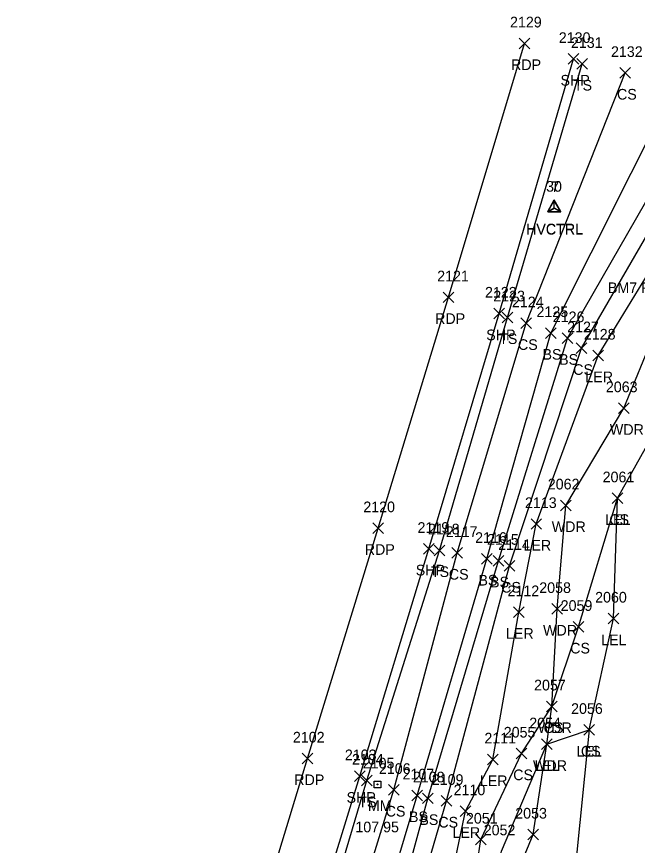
# Model space of a CAD drawing. Extents: x 1483143 to 1488182, y 802902 to 807581.
# Drawn here: x 1487999.7 to 1488116.3, y 807041.9 to 807197.5 of the extents above; entities that cross this region are included whole.
import ezdxf

# ---------------------------------------------------------------- set-up
doc = ezdxf.new("R2010")
doc.units = 0
for name, color, linetype in [('C_A', 7, 'Continuous'), ('C_C', 7, 'Continuous'), ('C_I', 7, 'Continuous'), ('CPSM', 7, 'Continuous'), ('L_A', 7, 'Continuous'), ('L_I', 7, 'Continuous'), ('L_TIC', 7, 'Continuous'), ('LARO', 7, 'Continuous'), ('LAWA', 7, 'Continuous'), ('LELB', 7, 'Continuous'), ('P_A', 7, 'Continuous'), ('P_I', 7, 'Continuous'), ('P_TIC', 7, 'Continuous'), ('PET', 7, 'Continuous'), ('PSP', 7, 'Continuous'), ('S_A', 7, 'Continuous'), ('S_C', 7, 'Continuous'), ('S_I', 7, 'Continuous'), ('SRM', 7, 'Continuous')]:
    doc.layers.add(name, color=color, linetype=linetype)

msp = doc.modelspace()

# ---------------------------------------------------------------- linework, layer by layer
at = {"layer": 'CPSM'}
for p, q in [((1488099.44, 807160.93), (1488100.69, 807163.1)), ((1488099.44, 807160.86), (1488100.69, 807163.02)), ((1488101.94, 807160.93), (1488100.69, 807163.1)), ((1488100.69, 807161.65), (1488100.69, 807163.1)), ((1488101.94, 807160.86), (1488100.69, 807163.02)), ((1488100.69, 807161.58), (1488100.69, 807163.02)), ((1488099.44, 807160.93), (1488100.69, 807161.65)), ((1488099.44, 807160.86), (1488100.69, 807161.58)), ((1488099.44, 807160.93), (1488101.94, 807160.93)), ((1488099.44, 807160.86), (1488101.94, 807160.86)), ((1488100.69, 807161.65), (1488100.69, 807161.65)), ((1488100.69, 807161.65), (1488101.94, 807160.93)), ((1488100.69, 807161.58), (1488100.69, 807161.58)), ((1488100.69, 807161.58), (1488101.94, 807160.86))]:
    msp.add_line(p, q, dxfattribs=at)
at = {"layer": 'L_TIC'}
for points in [[(1488104.94, 807187.64), (1488106.94, 807189.64)], [(1488106.94, 807187.64), (1488104.94, 807189.64)], [(1488113.02, 807185.94), (1488115.02, 807187.94)], [(1488115.02, 807185.94), (1488113.02, 807187.94)], [(1488090.92, 807140.06), (1488092.92, 807142.06)], [(1488092.92, 807140.06), (1488090.92, 807142.06)], [(1488094.42, 807138.95), (1488096.42, 807140.95)], [(1488096.42, 807138.95), (1488094.42, 807140.95)], [(1488099.03, 807137.12), (1488101.03, 807139.12)], [(1488101.03, 807137.12), (1488099.03, 807139.12)], [(1488102.15, 807136.16), (1488104.15, 807138.16)], [(1488104.15, 807136.16), (1488102.15, 807138.16)], [(1488104.79, 807134.26), (1488106.79, 807136.26)], [(1488106.79, 807134.26), (1488104.79, 807136.26)], [(1488107.93, 807132.89), (1488109.93, 807134.89)], [(1488109.93, 807132.89), (1488107.93, 807134.89)], [(1488112.75, 807123.01), (1488114.75, 807125.01)], [(1488114.75, 807123.01), (1488112.75, 807125.01)], [(1488111.58, 807106.1), (1488113.58, 807108.1)], [(1488113.58, 807106.1), (1488111.58, 807108.1)], [(1488111.58, 807106.1), (1488113.58, 807108.1)], [(1488113.58, 807106.1), (1488111.58, 807108.1)], [(1488101.84, 807104.76), (1488103.84, 807106.76)], [(1488103.84, 807104.76), (1488101.84, 807106.76)], [(1488096.31, 807101.27), (1488098.31, 807103.27)], [(1488098.31, 807101.27), (1488096.31, 807103.27)], [(1488078.1, 807096.32), (1488080.1, 807098.32)], [(1488080.1, 807096.32), (1488078.1, 807098.32)], [(1488081.44, 807095.83), (1488083.44, 807097.83)], [(1488083.44, 807095.83), (1488081.44, 807097.83)], [(1488087, 807094.72), (1488089, 807096.72)], [(1488089, 807094.72), (1488087, 807096.72)], [(1488089.18, 807094.37), (1488091.18, 807096.37)], [(1488091.18, 807094.37), (1488089.18, 807096.37)], [(1488091.26, 807093.39), (1488093.26, 807095.39)], [(1488093.26, 807093.39), (1488091.26, 807095.39)], [(1488093.03, 807084.72), (1488095.03, 807086.72)], [(1488095.03, 807084.72), (1488093.03, 807086.72)], [(1488100.2, 807085.32), (1488102.2, 807087.32)], [(1488102.2, 807085.32), (1488100.2, 807087.32)], [(1488110.83, 807083.52), (1488112.83, 807085.52)], [(1488112.83, 807083.52), (1488110.83, 807085.52)], [(1488104.23, 807081.96), (1488106.23, 807083.96)], [(1488106.23, 807081.96), (1488104.23, 807083.96)], [(1488099.23, 807067.03), (1488101.23, 807069.03)], [(1488101.23, 807067.03), (1488099.23, 807069.03)], [(1488099.23, 807067.03), (1488101.23, 807069.03)], [(1488101.23, 807067.03), (1488099.23, 807069.03)], [(1488106.24, 807062.62), (1488108.24, 807064.62)], [(1488108.24, 807062.62), (1488106.24, 807064.62)], [(1488106.24, 807062.62), (1488108.24, 807064.62)], [(1488108.24, 807062.62), (1488106.24, 807064.62)], [(1488098.31, 807059.91), (1488100.31, 807061.91)], [(1488100.31, 807059.91), (1488098.31, 807061.91)], [(1488098.31, 807059.91), (1488100.31, 807061.91)], [(1488100.31, 807059.91), (1488098.31, 807061.91)], [(1488093.53, 807058.18), (1488095.53, 807060.18)], [(1488095.53, 807058.18), (1488093.53, 807060.18)], [(1488088.12, 807057.07), (1488090.12, 807059.07)], [(1488090.12, 807057.07), (1488088.12, 807059.07)], [(1488064.46, 807053.1), (1488066.46, 807055.1)], [(1488066.46, 807053.1), (1488064.46, 807055.1)], [(1488069.58, 807051.35), (1488071.58, 807053.35)], [(1488071.58, 807051.35), (1488069.58, 807053.35)], [(1488073.95, 807050.31), (1488075.95, 807052.31)], [(1488075.95, 807050.31), (1488073.95, 807052.31)], [(1488075.91, 807049.77), (1488077.91, 807051.77)], [(1488077.91, 807049.77), (1488075.91, 807051.77)], [(1488079.46, 807049.29), (1488081.46, 807051.29)], [(1488081.46, 807049.29), (1488079.46, 807051.29)], [(1488082.99, 807047.35), (1488084.99, 807049.35)], [(1488084.99, 807047.35), (1488082.99, 807049.35)], [(1488095.69, 807042.97), (1488097.69, 807044.97)], [(1488097.69, 807042.97), (1488095.69, 807044.97)], [(1488085.86, 807042.03), (1488087.86, 807044.03)], [(1488087.86, 807042.03), (1488085.86, 807044.03)]]:
    msp.add_lwpolyline(points, dxfattribs=at)
at = {"layer": 'LARO'}
for points in [[(1488037.4, 806905.47), (1488041.65, 806915.63), (1488047.6, 806920.57), (1488046.62, 806934.71), (1488052.04, 806951.56), (1488058.64, 806974.33), (1488067.63, 806991.16), (1488072.23, 806999.37), (1488073.8, 807008.16), (1488079.91, 807014.12), (1488080.77, 807032.91), (1488083.99, 807048.35), (1488089.12, 807058.07), (1488094.03, 807085.72), (1488097.31, 807102.27), (1488108.93, 807133.89), (1488121.99, 807155.3), (1488125.4, 807152.3), (1488130.41, 807144.38)], [(1488050.72, 806901.7), (1488054.57, 806915.09), (1488058.39, 806925.38), (1488058.38, 806932.99), (1488064.32, 806951.27), (1488070.59, 806959.46), (1488072.37, 806972.02), (1488078.48, 806986.93), (1488088.4, 807009.21), (1488088, 807029.33), (1488090.77, 807040.83), (1488099.31, 807060.91), (1488107.24, 807063.62), (1488111.83, 807084.52), (1488112.58, 807107.1), (1488120.46, 807121.22), (1488130.41, 807144.38)]]:
    msp.add_lwpolyline(points, dxfattribs=at)
at = {"layer": 'LAWA'}
msp.add_lwpolyline([(1488060.09, 806903.93), (1488066.6, 806927.09), (1488073.94, 806954.77), (1488083.55, 806972.96), (1488088.27, 806995.8), (1488088.4, 807009.21), (1488090.5, 807029.04), (1488096.69, 807043.97), (1488099.31, 807060.91), (1488100.23, 807068.03), (1488101.2, 807086.32), (1488102.84, 807105.76), (1488113.75, 807124.01), (1488125.4, 807152.3), (1488136.51, 807165.24), (1488139.33, 807176.91)], dxfattribs=at)
at = {"layer": 'LELB'}
for points in [[(1487827.52, 806379.6), (1487850.09, 806437.73), (1487867.87, 806481.84), (1487885.56, 806528.78), (1487894.77, 806554.11), (1487911.86, 806599.05), (1487925.11, 806635.03), (1487938.6, 806672.73), (1487954.13, 806715.2), (1487966.77, 806750.86), (1487982.82, 806798.37), (1488000.33, 806849.53), (1488013.76, 806891.57), (1488028.96, 806936.12), (1488043.22, 806981), (1488053.37, 807013.21), (1488065.46, 807054.1), (1488079.1, 807097.32), (1488091.92, 807141.06), (1488105.94, 807188.64)], [(1487831.61, 806378.23), (1487855.61, 806436.65), (1487873.41, 806477.14), (1487888.61, 806527.7), (1487900.29, 806552.66), (1487915.56, 806597.3), (1487929.53, 806633.53), (1487942.79, 806670.21), (1487957.7, 806713.57), (1487969.99, 806749.64), (1487987.61, 806796.79), (1487994.35, 806813.4), (1488006.31, 806847.85), (1488017.75, 806890.1), (1488033.51, 806934.67), (1488047.05, 806979.87), (1488058.1, 807011.89), (1488070.58, 807052.35), (1488082.44, 807096.83), (1488095.42, 807139.95), (1488114.02, 807186.94)], [(1487835.19, 806376.59), (1487859.78, 806434.97), (1487877.62, 806477.28), (1487892.57, 806526.23), (1487904.08, 806551.45), (1487919.68, 806595.15), (1487934.47, 806632.17), (1487947.69, 806668.31), (1487962.32, 806711.59), (1487973.69, 806748.32), (1487991.68, 806795.65), (1487997.75, 806809.49), (1487999.54, 806813.18), (1488009.67, 806846.56), (1488021.34, 806888.06), (1488037.67, 806932.78), (1488051.91, 806977.51), (1488062.67, 807010.29), (1488074.95, 807051.31), (1488088, 807095.72), (1488100.03, 807138.12), (1488122.67, 807183.2)], [(1487837.5, 806376), (1487863.45, 806433.38), (1487880.32, 806475.86), (1487894.61, 806525.53), (1487906.02, 806551.4), (1487922.48, 806594.15), (1487937, 806631.99), (1487949.11, 806668.02), (1487964.79, 806711), (1487978.4, 806746.47), (1487994.99, 806794.38), (1488000.35, 806808.82), (1488001.34, 806812.09), (1488011.23, 806845.63), (1488024.65, 806886.78), (1488040.19, 806931.5), (1488054.27, 806976.88), (1488065.68, 807009.57), (1488076.91, 807050.77), (1488090.18, 807095.37), (1488103.15, 807137.16), (1488127.49, 807179.54)], [(1487839.66, 806374.66), (1487865.87, 806433.14), (1487881.15, 806476.22), (1487897.55, 806523.91), (1487908.57, 806550.53), (1487926.89, 806591.97), (1487940.49, 806630.59), (1487952.54, 806666.3), (1487966.7, 806710.04), (1487981.74, 806745.96), (1487997.33, 806793.52), (1488011.64, 806832), (1488027.95, 806886.11), (1488041.92, 806927.39), (1488045.38, 806935.91), (1488056.2, 806975.87), (1488068.38, 807008.79), (1488080.46, 807050.29), (1488092.26, 807094.39), (1488105.79, 807135.26), (1488129.48, 807176.06)], [(1488043.93, 806905.8), (1488054.57, 806915.09), (1488048.86, 806918.51), (1488050.26, 806926.52), (1488054.26, 806940.91), (1488057.32, 806952.68), (1488061.43, 806965.52), (1488065.26, 806978.26), (1488072.35, 806989.31), (1488077.56, 806999.25), (1488084.51, 807008.67), (1488084.83, 807029.18), (1488086.86, 807043.03), (1488094.53, 807059.18), (1488100.23, 807068.03), (1488105.23, 807082.96), (1488112.58, 807107.1)], [(1488107.24, 807063.62), (1488102.78, 807019.53), (1488102.52, 806993.48), (1488098.25, 806971.93), (1488100.18, 806941.81), (1488099.28, 806926.81), (1488086.46, 806896.83), (1488081.97, 806885.84), (1488071.39, 806887.6), (1488071.71, 806872.37), (1488064.05, 806852.05), (1488068.8, 806843.92), (1488067.03, 806830.27), (1488057.62, 806804.31), (1488039.63, 806814.37), (1488034.14, 806816.99), (1488041.4, 806825.04)]]:
    msp.add_lwpolyline(points, dxfattribs=at)
at = {"layer": 'P_TIC'}
for points in [[(1488094.07, 807191.49), (1488096.07, 807193.49)], [(1488096.07, 807191.49), (1488094.07, 807193.49)], [(1488103.31, 807188.57), (1488105.31, 807190.57)], [(1488105.31, 807188.57), (1488103.31, 807190.57)], [(1488079.81, 807143.82), (1488081.81, 807145.82)], [(1488081.81, 807143.82), (1488079.81, 807145.82)], [(1488089.36, 807140.77), (1488091.36, 807142.77)], [(1488091.36, 807140.77), (1488089.36, 807142.77)], [(1488066.6, 807100.48), (1488068.6, 807102.48)], [(1488068.6, 807100.48), (1488066.6, 807102.48)], [(1488076.14, 807096.61), (1488078.14, 807098.61)], [(1488078.14, 807096.61), (1488076.14, 807098.61)], [(1488053.37, 807057.25), (1488055.37, 807059.25)], [(1488055.37, 807057.25), (1488053.37, 807059.25)], [(1488063.14, 807053.93), (1488065.14, 807055.93)], [(1488065.14, 807053.93), (1488063.14, 807055.93)]]:
    msp.add_lwpolyline(points, dxfattribs=at)
at = {"layer": 'PET'}
msp.add_lwpolyline([(1487817.05, 806384.04), (1487839.67, 806441.4), (1487857.48, 806486.15), (1487875.5, 806533.55), (1487884.95, 806558.16), (1487901.52, 806603.65), (1487914.56, 806639.6), (1487927.99, 806676.8), (1487943.06, 806720.01), (1487955.19, 806754.64), (1487971.37, 806801.63), (1487988.85, 806854.11), (1488002.85, 806896.07), (1488017.7, 806940.87), (1488031.56, 806984.9), (1488041.8, 807017.08), (1488054.37, 807058.25), (1488067.6, 807101.48), (1488080.81, 807144.82), (1488095.07, 807192.49)], dxfattribs=at)
at = {"layer": 'PSP'}
msp.add_lwpolyline([(1487825.55, 806380.21), (1487847.81, 806437.56), (1487866.19, 806483.39), (1487884.04, 806529.78), (1487893.44, 806554.46), (1487910.05, 806599.89), (1487923.16, 806635.65), (1487936.98, 806673.57), (1487951.99, 806715.79), (1487964.7, 806751.7), (1487980.81, 806798.97), (1487998.23, 806850.18), (1488012.19, 806892.24), (1488027.11, 806936.91), (1488041.21, 806981.53), (1488051.31, 807013.35), (1488064.14, 807054.93), (1488077.14, 807097.61), (1488090.36, 807141.77), (1488104.31, 807189.57)], dxfattribs=at)
at = {"layer": 'SRM'}
msp.add_lwpolyline([(1488066.86, 807054.02), (1488068.11, 807054.02), (1488068.11, 807052.77), (1488066.86, 807052.77)], close=True, dxfattribs=at)
msp.add_circle((1488067.48, 807053.39), 0.0833, dxfattribs=at)

# ---------------------------------------------------------------- texts
at = {"layer": 'C_A'}
for p in [(1488095.38, 807156.65), (1488095.38, 807156.58)]:
    msp.add_text('HVCTRL', height=2, dxfattribs=at).set_placement(p)
at = {"layer": 'C_C'}
msp.add_text('BM7 RRSIR M.ASH ELV', height=2, dxfattribs=at).set_placement((1488110.75, 807145.62))
at = {"layer": 'C_I'}
for s, p in [('30', (1488099.14, 807164.65)), ('7', (1488100.12, 807164.58))]:
    msp.add_text(s, height=2, dxfattribs=at).set_placement(p)
at = {"layer": 'L_A'}
for s, p in [('TS', (1488104.35, 807183.64)), ('CS', (1488112.46, 807181.94)), ('TS', (1488090.33, 807136.06)), ('CS', (1488093.86, 807134.95)), ('BS', (1488098.47, 807133.12)), ('BS', (1488101.59, 807132.16)), ('CS', (1488104.23, 807130.26)), ('LER', (1488106.51, 807128.89)), ('WDR', (1488111.12, 807119.01)), ('LEL', (1488110.22, 807102.1)), ('CS', (1488111.02, 807102.1)), ('WDR', (1488100.2, 807100.76)), ('LER', (1488094.89, 807097.27)), ('TS', (1488077.51, 807092.32)), ('CS', (1488080.88, 807091.83)), ('BS', (1488086.44, 807090.72)), ('BS', (1488088.62, 807090.37)), ('CS', (1488090.7, 807089.39)), ('WDR', (1488098.57, 807081.32)), ('LER', (1488091.61, 807080.72)), ('LEL', (1488109.47, 807079.52)), ('CS', (1488103.67, 807077.96)), ('WDR', (1488097.59, 807063.03)), ('CS', (1488098.67, 807063.03)), ('LEL', (1488104.87, 807058.62)), ('CS', (1488105.68, 807058.62)), ('WDR', (1488096.68, 807055.91)), ('LEL', (1488096.95, 807055.91)), ('LER', (1488086.7, 807053.07)), ('CS', (1488092.97, 807054.18)), ('TS', (1488063.87, 807049.1)), ('CS', (1488069.02, 807047.35)), ('BS', (1488073.39, 807046.31)), ('BS', (1488075.35, 807045.77)), ('CS', (1488078.91, 807045.29)), ('LER', (1488081.57, 807043.35))]:
    msp.add_text(s, height=2, dxfattribs=at).set_placement(p)
at = {"layer": 'L_I'}
for s, p in [('2131', (1488103.81, 807191.64)), ('2132', (1488111.33, 807189.94)), ('2123', (1488089.23, 807144.06)), ('2124', (1488092.73, 807142.95)), ('2125', (1488097.34, 807141.12)), ('2126', (1488100.4, 807140.16)), ('2127', (1488103.1, 807138.26)), ('2128', (1488106.24, 807136.89)), ('2063', (1488110.37, 807127.01)), ('2061', (1488109.76, 807110.1)), ('2061', (1488109.76, 807110.1)), ('2062', (1488099.46, 807108.76)), ('2113', (1488095.18, 807105.27)), ('2118', (1488076.97, 807100.32)), ('2117', (1488080.32, 807099.83)), ('2116', (1488085.82, 807098.72)), ('2115', (1488088.05, 807098.37)), ('2114', (1488090.14, 807097.39)), ('2058', (1488097.86, 807089.32)), ('2112', (1488091.9, 807088.72)), ('2060', (1488108.35, 807087.52)), ('2059', (1488101.88, 807085.96)), ('2057', (1488096.89, 807071.03)), ('2057', (1488096.89, 807071.03)), ('2056', (1488103.84, 807066.62)), ('2056', (1488103.84, 807066.62)), ('2054', (1488095.98, 807063.91)), ('2054', (1488095.98, 807063.91)), ('2111', (1488087.56, 807061.07)), ('2055', (1488091.19, 807062.18)), ('2104', (1488062.69, 807057.1)), ('2106', (1488067.75, 807055.35)), ('2107', (1488072.18, 807054.31)), ('2108', (1488074.14, 807053.77)), ('2109', (1488077.68, 807053.29)), ('2110', (1488081.78, 807051.35)), ('2053', (1488093.35, 807046.97)), ('2051', (1488084.09, 807046.03)), ('2052', (1488087.43, 807043.83))]:
    msp.add_text(s, height=2, dxfattribs=at).set_placement(p)
at = {"layer": 'P_A'}
for s, p in [('RDP', (1488092.56, 807187.49)), ('SHP', (1488101.85, 807184.57)), ('RDP', (1488078.3, 807139.82)), ('SHP', (1488087.9, 807136.77)), ('RDP', (1488065.09, 807096.48)), ('SHP', (1488074.67, 807092.61)), ('RDP', (1488051.86, 807053.25)), ('SHP', (1488061.67, 807049.93))]:
    msp.add_text(s, height=2, dxfattribs=at).set_placement(p)
at = {"layer": 'P_I'}
for s, p in [('2129', (1488092.37, 807195.49)), ('2130', (1488101.53, 807192.57)), ('2121', (1488078.69, 807147.82)), ('2122', (1488087.67, 807144.77)), ('2120', (1488064.82, 807104.48)), ('2119', (1488075, 807100.61)), ('2102', (1488051.6, 807061.25)), ('2103', (1488061.36, 807057.93))]:
    msp.add_text(s, height=2, dxfattribs=at).set_placement(p)
at = {"layer": 'S_A'}
msp.add_text('MM', height=2, dxfattribs=at).set_placement((1488065.67, 807048.39))
at = {"layer": 'S_C'}
msp.add_text('107.95', height=2, dxfattribs=at).set_placement((1488063.33, 807044.39))
at = {"layer": 'S_I'}
msp.add_text('2105', height=2, dxfattribs=at).set_placement((1488064.71, 807056.39))

doc.saveas('drawing.dxf')
